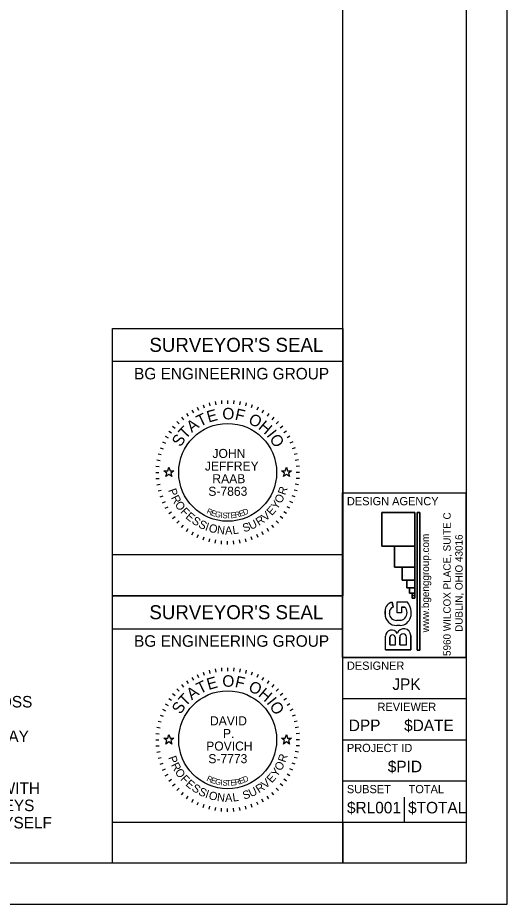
# Model space of a CAD drawing. Extents: x 0 to 34, y 0 to 22.
# Drawn here: x 28.05 to 34, y 0 to 10.78 of the extents above; entities that cross this region are included whole.
import ezdxf

# ---------------------------------------------------------------- set-up
doc = ezdxf.new("R2010")
doc.units = 0
for name, color, linetype in [('SC_Scratch1', 7, 'Continuous'), ('SH_Border', 7, 'Continuous'), ('SH_Cut_Line', 7, 'Continuous'), ('SH_Data', 7, 'Continuous'), ('SH_Text', 7, 'Continuous')]:
    doc.layers.add(name, color=color, linetype=linetype)

msp = doc.modelspace()

# ---------------------------------------------------------------- linework, layer by layer
at = {"layer": 'SC_Scratch1'}
msp.add_lwpolyline([(31.998, 5), (33.498, 5), (33.498, 3), (31.998, 3)], close=True, dxfattribs=at)
at = {"layer": 'SH_Border'}
for p, q in [((32, 0.5), (32, 21.5)), ((32, 5), (33.5, 5)), ((32, 3), (33.5, 3)), ((32, 2.5), (33.5, 2.5)), ((32, 2), (33.5, 2)), ((32, 1.5), (33.5, 1.5)), ((32, 1), (33.5, 1))]:
    msp.add_line(p, q, dxfattribs=at)
msp.add_lwpolyline([(1.5, 21.5), (33.5, 21.5), (33.5, 0.5), (1.5, 0.5)], close=True, dxfattribs=at)
at = {"layer": 'SH_Cut_Line'}
msp.add_lwpolyline([(0, 0), (34, 0), (34, 22), (0, 22)], close=True, dxfattribs=at)
at = {"layer": 'SH_Data'}
for p, q in [((29.2, 3.75), (29.2, 7)), ((29.2, 7), (32, 7)), ((32, 7), (32, 3.75)), ((29.2, 6.6), (32, 6.6)), ((32.875, 4.352), (32.875, 4.764)), ((32.875, 4.099), (32.875, 4.352)), ((32.875, 3.941), (32.875, 4.099)), ((32.75, 4), (32.75, 4)), ((32.875, 3.847), (32.875, 3.941)), ((32.875, 3.783), (32.875, 3.847)), ((32.875, 3.752), (32.875, 3.783)), ((29.2, 3.75), (32, 3.75)), ((29.2, 0.5), (29.2, 3.75)), ((29.2, 3.75), (32, 3.75)), ((32.613, 3.61), (32.6, 3.671)), ((32.6, 3.671), (32.613, 3.61)), ((32.875, 3.72), (32.875, 3.752)), ((32.514, 3.565), (32.514, 3.528)), ((32.514, 3.528), (32.514, 3.565)), ((32.713, 3.613), (32.753, 3.613)), ((32.566, 3.551), (32.566, 3.536)), ((32.566, 3.551), (32.566, 3.536)), ((32.697, 3.452), (32.653, 3.451)), ((32.653, 3.451), (32.697, 3.452)), ((29.2, 3.35), (32, 3.35)), ((32.698, 3.39), (32.657, 3.389)), ((32.698, 3.39), (32.657, 3.389)), ((32.519, 3.093), (32.519, 3.257)), ((32.57, 3.155), (32.57, 3.239)), ((32.692, 3.155), (32.692, 3.245)), ((32.75, 1), (32.75, 1.3))]:
    msp.add_line(p, q, dxfattribs=at)
for points in [[(32.475, 4.352), (32.475, 4.764), (32.875, 4.764), (32.875, 4.352)], [(32.904, 3.088), (32.935, 3.088), (32.935, 4.764), (32.904, 4.764)], [(32.904, 4.764), (32.935, 4.764), (32.935, 3.088), (32.904, 3.088)], [(32.628, 4.099), (32.628, 4.352), (32.875, 4.352), (32.875, 4.099)], [(29.2, 3.75), (29.2, 4.25), (32, 4.25), (32, 3.75)], [(32.72, 3.941), (32.72, 4.099), (32.875, 4.099), (32.875, 3.941)], [(32.875, 3.941), (32.875, 3.847), (32.78, 3.847), (32.78, 3.941)], [(32.812, 3.783), (32.812, 3.847), (32.875, 3.847), (32.875, 3.783)], [(32.842, 3.752), (32.842, 3.783), (32.875, 3.783), (32.875, 3.752)], [(32.875, 3.72), (32.842, 3.72), (32.842, 3.752), (32.875, 3.752)], [(29.2, 0.5), (29.2, 1), (32, 1), (32, 0.5)]]:
    msp.add_lwpolyline(points, close=True, dxfattribs=at)
for points in [[(32.875, 4.764), (32.475, 4.764), (32.475, 4.352), (32.875, 4.352)], [(32.875, 4.352), (32.628, 4.352), (32.628, 4.099), (32.875, 4.099)], [(32.875, 4.099), (32.72, 4.099), (32.72, 3.941), (32.875, 3.941)], [(32.875, 3.941), (32.78, 3.941), (32.78, 3.847), (32.875, 3.847)], [(32.875, 3.847), (32.812, 3.847), (32.812, 3.783), (32.875, 3.783)], [(32.875, 3.783), (32.842, 3.783), (32.842, 3.752), (32.875, 3.752)], [(32.713, 3.613), (32.713, 3.541), (32.662, 3.541), (32.662, 3.675), (32.784, 3.675)], [(32.753, 3.613), (32.713, 3.613), (32.713, 3.541), (32.662, 3.541), (32.662, 3.675), (32.784, 3.675)], [(32.875, 3.752), (32.842, 3.752), (32.842, 3.72), (32.875, 3.72)], [(32.519, 3.093), (32.826, 3.093), (32.826, 3.266)], [(32.826, 3.266), (32.826, 3.093), (32.519, 3.093), (32.519, 3.257)], [(32.57, 3.155), (32.641, 3.155), (32.641, 3.239)], [(32.57, 3.239), (32.57, 3.155), (32.641, 3.155), (32.641, 3.239)], [(32.692, 3.155), (32.774, 3.155), (32.774, 3.245)], [(32.692, 3.245), (32.692, 3.155), (32.774, 3.155), (32.774, 3.245)]]:
    msp.add_lwpolyline(points, dxfattribs=at)
for centre, radius, start, end in [((32.623, 3.565), 0.109, 101.8306, 180), ((32.623, 3.565), 0.109, 101.8306, 180), ((32.626, 3.543), 0.206, 344.319, 39.7523), ((32.626, 3.543), 0.206, 344.319, 39.7523), ((32.625, 3.552), 0.0591, 101.8306, 180.9132), ((32.625, 3.552), 0.0591, 101.8306, 180.9132), ((32.683, 3.545), 0.0981, 315.8822, 44.1178), ((32.683, 3.545), 0.0981, 315.8822, 44.1178), ((32.653, 3.528), 0.139, 180, 271.4276), ((32.653, 3.528), 0.139, 180, 271.4276), ((32.651, 3.536), 0.0852, 180, 271.4276), ((32.651, 3.536), 0.0852, 180, 271.4276), ((32.695, 3.534), 0.0816, 271.4276, 315.8822), ((32.695, 3.534), 0.0816, 271.4276, 315.8822), ((32.695, 3.524), 0.134, 271.4276, 344.319), ((32.695, 3.524), 0.134, 271.4276, 344.319), ((32.742, 3.266), 0.0837, 360, 162.1627), ((32.742, 3.266), 0.0837, 360, 162.1627), ((32.595, 3.257), 0.0759, 27.219, 180), ((32.595, 3.257), 0.0759, 27.219, 180), ((32.605, 3.239), 0.0353, 0, 180), ((32.605, 3.239), 0.0353, 0, 180), ((32.733, 3.245), 0.0414, 0, 180), ((32.733, 3.245), 0.0414, 0, 180)]:
    msp.add_arc(centre, radius, start, end, dxfattribs=at)
at = {"layer": 'SH_Text'}
for p, q in [((30.23, 6.043), (30.247, 6.007)), ((30.301, 6.072), (30.314, 6.035)), ((30.374, 6.095), (30.384, 6.057)), ((30.448, 6.112), (30.455, 6.072)), ((30.524, 6.122), (30.527, 6.082)), ((30.6, 6.125), (30.6, 6.085)), ((30.676, 6.122), (30.673, 6.082)), ((30.752, 6.112), (30.745, 6.072)), ((30.826, 6.095), (30.816, 6.057)), ((30.899, 6.072), (30.886, 6.035)), ((30.97, 6.043), (30.953, 6.007)), ((30.098, 5.967), (30.121, 5.934)), ((30.163, 6.008), (30.183, 5.973)), ((31.037, 6.008), (31.017, 5.973)), ((31.102, 5.967), (31.079, 5.934)), ((29.981, 5.869), (30.01, 5.84)), ((30.038, 5.92), (30.063, 5.89)), ((31.162, 5.92), (31.137, 5.89)), ((31.219, 5.869), (31.19, 5.84)), ((29.883, 5.752), (29.916, 5.729)), ((29.93, 5.812), (29.96, 5.787)), ((31.27, 5.812), (31.24, 5.787)), ((31.317, 5.752), (31.284, 5.729)), ((29.807, 5.62), (29.843, 5.603)), ((29.842, 5.688), (29.877, 5.668)), ((31.358, 5.688), (31.323, 5.668)), ((31.393, 5.62), (31.357, 5.603)), ((29.778, 5.549), (29.815, 5.536)), ((31.422, 5.549), (31.385, 5.536)), ((29.738, 5.402), (29.778, 5.395)), ((29.755, 5.476), (29.793, 5.466)), ((31.445, 5.476), (31.407, 5.466)), ((31.462, 5.402), (31.422, 5.395)), ((29.728, 5.326), (29.768, 5.323)), ((31.472, 5.326), (31.432, 5.323)), ((29.725, 5.25), (29.765, 5.25)), ((29.728, 5.174), (29.768, 5.177)), ((31.472, 5.174), (31.432, 5.177)), ((31.475, 5.25), (31.435, 5.25)), ((29.738, 5.098), (29.778, 5.105)), ((31.462, 5.098), (31.422, 5.105)), ((29.755, 5.024), (29.793, 5.034)), ((29.778, 4.951), (29.815, 4.964)), ((31.422, 4.951), (31.385, 4.964)), ((31.445, 5.024), (31.407, 5.034)), ((29.807, 4.88), (29.843, 4.897)), ((31.393, 4.88), (31.357, 4.897)), ((29.842, 4.813), (29.877, 4.833)), ((29.883, 4.748), (29.916, 4.771)), ((31.317, 4.748), (31.284, 4.771)), ((31.358, 4.813), (31.323, 4.833)), ((29.93, 4.688), (29.96, 4.713)), ((29.981, 4.631), (30.01, 4.66)), ((31.219, 4.631), (31.19, 4.66)), ((31.27, 4.688), (31.24, 4.713)), ((30.038, 4.58), (30.063, 4.61)), ((30.098, 4.533), (30.121, 4.566)), ((30.163, 4.492), (30.183, 4.527)), ((31.037, 4.492), (31.017, 4.527)), ((31.102, 4.533), (31.079, 4.566)), ((31.162, 4.58), (31.137, 4.61)), ((30.23, 4.457), (30.247, 4.493)), ((30.301, 4.428), (30.314, 4.465)), ((30.374, 4.405), (30.384, 4.443)), ((30.448, 4.388), (30.455, 4.428)), ((30.752, 4.388), (30.745, 4.428)), ((30.826, 4.405), (30.816, 4.443)), ((30.899, 4.428), (30.886, 4.465)), ((30.97, 4.457), (30.953, 4.493)), ((30.524, 4.378), (30.527, 4.418)), ((30.6, 4.375), (30.6, 4.415)), ((30.676, 4.378), (30.673, 4.418)), ((30.301, 2.822), (30.314, 2.785)), ((30.374, 2.845), (30.384, 2.807)), ((30.448, 2.862), (30.455, 2.822)), ((30.524, 2.872), (30.527, 2.832)), ((30.6, 2.875), (30.6, 2.835)), ((30.676, 2.872), (30.673, 2.832)), ((30.752, 2.862), (30.745, 2.822)), ((30.826, 2.845), (30.816, 2.807)), ((30.899, 2.822), (30.886, 2.785)), ((30.098, 2.717), (30.121, 2.684)), ((30.163, 2.758), (30.183, 2.723)), ((30.23, 2.793), (30.247, 2.757)), ((30.97, 2.793), (30.953, 2.757)), ((31.037, 2.758), (31.017, 2.723)), ((31.102, 2.717), (31.079, 2.684)), ((29.981, 2.619), (30.01, 2.59)), ((30.038, 2.67), (30.063, 2.64)), ((31.162, 2.67), (31.137, 2.64)), ((31.219, 2.619), (31.19, 2.59)), ((29.883, 2.502), (29.916, 2.479)), ((29.93, 2.562), (29.96, 2.537)), ((31.27, 2.562), (31.24, 2.537)), ((31.317, 2.502), (31.284, 2.479)), ((29.842, 2.438), (29.877, 2.418)), ((31.358, 2.438), (31.323, 2.418)), ((29.778, 2.299), (29.815, 2.286)), ((29.807, 2.37), (29.843, 2.353)), ((31.393, 2.37), (31.357, 2.353)), ((31.422, 2.299), (31.385, 2.286)), ((29.755, 2.226), (29.793, 2.216)), ((31.445, 2.226), (31.407, 2.216)), ((29.728, 2.076), (29.768, 2.073)), ((29.738, 2.152), (29.778, 2.145)), ((31.462, 2.152), (31.422, 2.145)), ((31.472, 2.076), (31.432, 2.073)), ((29.725, 2), (29.765, 2)), ((31.475, 2), (31.435, 2)), ((29.728, 1.924), (29.768, 1.927)), ((29.738, 1.848), (29.778, 1.855)), ((31.462, 1.848), (31.422, 1.855)), ((31.472, 1.924), (31.432, 1.927)), ((29.755, 1.774), (29.793, 1.784)), ((31.445, 1.774), (31.407, 1.784)), ((29.778, 1.701), (29.815, 1.714)), ((29.807, 1.63), (29.843, 1.647)), ((31.393, 1.63), (31.357, 1.647)), ((31.422, 1.701), (31.385, 1.714)), ((29.842, 1.563), (29.877, 1.583)), ((29.883, 1.498), (29.916, 1.521)), ((31.317, 1.498), (31.284, 1.521)), ((31.358, 1.563), (31.323, 1.583)), ((29.93, 1.438), (29.96, 1.463)), ((29.981, 1.381), (30.01, 1.41)), ((31.219, 1.381), (31.19, 1.41)), ((31.27, 1.438), (31.24, 1.463)), ((30.038, 1.33), (30.063, 1.36)), ((30.098, 1.283), (30.121, 1.316)), ((31.102, 1.283), (31.079, 1.316)), ((31.162, 1.33), (31.137, 1.36)), ((30.163, 1.242), (30.183, 1.277)), ((30.23, 1.207), (30.247, 1.243)), ((30.301, 1.178), (30.314, 1.215)), ((30.374, 1.155), (30.384, 1.193)), ((30.826, 1.155), (30.816, 1.193)), ((30.899, 1.178), (30.886, 1.215)), ((30.97, 1.207), (30.953, 1.243)), ((31.037, 1.242), (31.017, 1.277)), ((30.448, 1.138), (30.455, 1.178)), ((30.524, 1.128), (30.527, 1.168)), ((30.6, 1.125), (30.6, 1.165)), ((30.676, 1.128), (30.673, 1.168)), ((30.752, 1.138), (30.745, 1.178))]:
    msp.add_line(p, q, dxfattribs=at)
for points in [[(29.824, 5.27), (29.871, 5.27), (29.885, 5.315), (29.899, 5.27), (29.946, 5.27), (29.908, 5.242), (29.923, 5.198), (29.885, 5.225), (29.847, 5.198), (29.862, 5.242)], [(31.254, 5.27), (31.301, 5.27), (31.315, 5.315), (31.329, 5.27), (31.376, 5.27), (31.338, 5.242), (31.353, 5.198), (31.315, 5.225), (31.277, 5.198), (31.292, 5.242)], [(29.824, 2.02), (29.871, 2.02), (29.885, 2.065), (29.899, 2.02), (29.946, 2.02), (29.908, 1.992), (29.923, 1.948), (29.885, 1.975), (29.847, 1.948), (29.862, 1.992)], [(31.254, 2.02), (31.301, 2.02), (31.315, 2.065), (31.329, 2.02), (31.376, 2.02), (31.338, 1.992), (31.353, 1.948), (31.315, 1.975), (31.277, 1.948), (31.292, 1.992)]]:
    msp.add_lwpolyline(points, close=True, dxfattribs=at)
for centre in [(30.6, 5.25), (30.6, 2)]:
    msp.add_circle(centre, 0.595, dxfattribs=at)

# ---------------------------------------------------------------- texts
at = {"layer": 'SH_Data'}
for s, height, p in [("SURVEYOR'S SEAL", 0.17, (29.648, 6.715)), ('BG ENGINEERING GROUP', 0.14, (29.462, 6.38)), ('DESIGN AGENCY', 0.1, (32.05, 4.85)), ("SURVEYOR'S SEAL", 0.17, (29.648, 3.465)), ('BG ENGINEERING GROUP', 0.14, (29.462, 3.13)), ('DESIGNER', 0.1, (32.05, 2.85)), ('JPK', 0.14, (32.603, 2.605)), ('REVIEWER', 0.1, (32.422, 2.35)), ('DPP', 0.14, (32.073, 2.105)), ('$DATE', 0.14, (32.746, 2.105)), ('PROJECT ID', 0.1, (32.05, 1.85)), ('$PID', 0.14, (32.547, 1.605)), ('SUBSET', 0.1, (32.05, 1.35)), ('TOTAL', 0.1, (32.8, 1.35)), ('$RL001', 0.14, (32.051, 1.105)), ('$TOTAL', 0.14, (32.794, 1.105))]:
    msp.add_text(s, height=height, dxfattribs=at).set_placement(p)
for s, p in [('5960 WILCOX PLACE, SUITE C', (33.312, 3.018)), ('www.bgenggroup.com', (33.049, 3.306)), ('DUBLIN, OHIO 43016', (33.457, 3.311))]:
    msp.add_text(s, height=0.09, rotation=90, dxfattribs=at).set_placement(p)
at = {"layer": 'SH_Text'}
for s, height, rotation, p in [('O', 0.14, 359.7812, (30.535, 5.894)), ('T', 0.14, 25.7167, (30.262, 5.802)), ('E', 0.14, 15.7571, (30.368, 5.854)), ('F', 0.14, 347.4362, (30.681, 5.892)), ('O', 0.14, 332.2586, (30.84, 5.852)), ('T', 0.14, 46.4344, (30.088, 5.646)), ('A', 0.14, 36.4747, (30.163, 5.728)), ('H', 0.14, 319.9136, (30.963, 5.786)), ('S', 0.14, 57.1924, (30.028, 5.551)), ('I', 0.14, 308.367, (31.066, 5.698)), ('O', 0.14, 303.1491, (31.102, 5.659)), ('R', 0.1, 70.983, (31.301, 4.967)), ('P', 0.1, 289.7431, (29.875, 5.034)), ('R', 0.1, 296.9802, (29.909, 4.943)), ('O', 0.1, 62.7428, (31.25, 4.863)), ('O', 0.1, 304.7158, (29.953, 4.858)), ('Y', 0.1, 55.5058, (31.2, 4.79)), ('F', 0.1, 312.956, (30.019, 4.766)), ('E', 0.1, 319.6885, (30.081, 4.7)), ('R', 0.07, 334.487, (30.337, 4.755)), ('E', 0.07, 341.04, (30.391, 4.73)), ('G', 0.07, 347.4752, (30.441, 4.712)), ('I', 0.07, 353.7858, (30.509, 4.697)), ('S', 0.07, 356.8926, (30.536, 4.693)), ('T', 0.07, 3.0061, (30.586, 4.689)), ('E', 0.07, 6.0117, (30.639, 4.691)), ('R', 0.07, 11.9184, (30.692, 4.697)), ('E', 0.07, 17.6836, (30.75, 4.71)), ('D', 0.07, 23.3052, (30.801, 4.727)), ('V', 0.1, 41.0316, (31.061, 4.651)), ('E', 0.1, 48.2687, (31.137, 4.717)), ('S', 0.1, 326.9255, (30.155, 4.639)), ('S', 0.1, 334.1626, (30.236, 4.587)), ('I', 0.1, 341.3997, (30.319, 4.548)), ('S', 0.1, 18.3234, (30.8, 4.521)), ('U', 0.1, 25.5604, (30.883, 4.549)), ('R', 0.1, 33.296, (30.981, 4.597)), ('O', 0.1, 345.1351, (30.362, 4.532)), ('N', 0.1, 353.3752, (30.466, 4.505)), ('A', 0.1, 1.1108, (30.569, 4.494)), ('L', 0.1, 8.3479, (30.666, 4.497)), ('T', 0.14, 25.7167, (30.262, 2.552)), ('E', 0.14, 15.7571, (30.368, 2.604)), ('O', 0.14, 359.7812, (30.535, 2.644)), ('F', 0.14, 347.4362, (30.681, 2.642)), ('O', 0.14, 332.2586, (30.84, 2.602)), ('A', 0.14, 36.4747, (30.163, 2.478)), ('H', 0.14, 319.9136, (30.963, 2.536)), ('T', 0.14, 46.4344, (30.088, 2.396)), ('I', 0.14, 308.367, (31.066, 2.448)), ('S', 0.14, 57.1924, (30.028, 2.301)), ('O', 0.14, 303.1491, (31.102, 2.409)), ('P', 0.1, 289.7431, (29.875, 1.784)), ('R', 0.1, 296.9802, (29.909, 1.693)), ('O', 0.1, 62.7428, (31.25, 1.613)), ('R', 0.1, 70.983, (31.301, 1.717)), ('O', 0.1, 304.7158, (29.953, 1.608)), ('Y', 0.1, 55.5058, (31.2, 1.54)), ('F', 0.1, 312.956, (30.019, 1.516)), ('E', 0.1, 319.6885, (30.081, 1.45)), ('R', 0.07, 334.487, (30.337, 1.505)), ('E', 0.07, 341.04, (30.391, 1.48)), ('G', 0.07, 347.4752, (30.441, 1.462)), ('I', 0.07, 353.7858, (30.509, 1.447)), ('S', 0.07, 356.8926, (30.536, 1.443)), ('T', 0.07, 3.0061, (30.586, 1.439)), ('E', 0.07, 6.0117, (30.639, 1.441)), ('R', 0.07, 11.9184, (30.692, 1.447)), ('E', 0.07, 17.6836, (30.75, 1.46)), ('D', 0.07, 23.3052, (30.801, 1.477)), ('V', 0.1, 41.0316, (31.061, 1.401)), ('E', 0.1, 48.2687, (31.137, 1.467)), ('S', 0.1, 326.9255, (30.155, 1.389)), ('S', 0.1, 334.1626, (30.236, 1.337)), ('U', 0.1, 25.5604, (30.883, 1.299)), ('R', 0.1, 33.296, (30.981, 1.347)), ('I', 0.1, 341.3997, (30.319, 1.298)), ('O', 0.1, 345.1351, (30.362, 1.282)), ('N', 0.1, 353.3752, (30.466, 1.255)), ('A', 0.1, 1.1108, (30.569, 1.244)), ('L', 0.1, 8.3479, (30.666, 1.247)), ('S', 0.1, 18.3234, (30.8, 1.271))]:
    msp.add_text(s, height=height, rotation=rotation, dxfattribs=at).set_placement(p)
for s, height, p in [('JOHN', 0.11, (30.415, 5.425)), ('JEFFREY', 0.11, (30.323, 5.272)), ('RAAB', 0.11, (30.414, 5.118)), ('S-7863', 0.11, (30.365, 4.965)), ('AS PART OF THIS PROJECT, I HAVE ESTABLISHED THE STANDARD HIGHWAY EASEMENTS, CALCULATED THE GROSS ', 0.14, (17.49, 2.392)), ('DAVID', 0.11, (30.385, 2.175)), ('DESCRIPTIONS NECESSARY TO ACQUIRE THE PARCELS SHOWN HEREIN. AS A PART OF THIS WORK, RIGHT OF WAY ', 0.14, (17.49, 1.972)), ('P.', 0.11, (30.542, 2.022)), ('POVICH', 0.11, (30.339, 1.868)), ('S-7773', 0.11, (30.365, 1.715)), ('TRANSPORTATION DATED 9-22-2010. ALL OF MY WORK CONTAINED HEREIN WAS CONDUCTED IN ACCORDANCE WITH ', 0.14, (17.49, 1.342)), ('THE OHIO ADMINISTRATIVE CODE 4733-37 COMMONLY KNOWN AS "MINIMUM STANDARDS FOR BOUNDARY SURVEYS ', 0.14, (17.49, 1.132)), ('IN THE STATE OF OHIO" UNLESS SO NOTED. THE WORDS"I "AND "MY", AS USED HEREIN, ARE TO MEAN EITHER MYSELF ', 0.14, (17.49, 0.922))]:
    msp.add_text(s, height=height, dxfattribs=at).set_placement(p)

doc.saveas('drawing.dxf')
